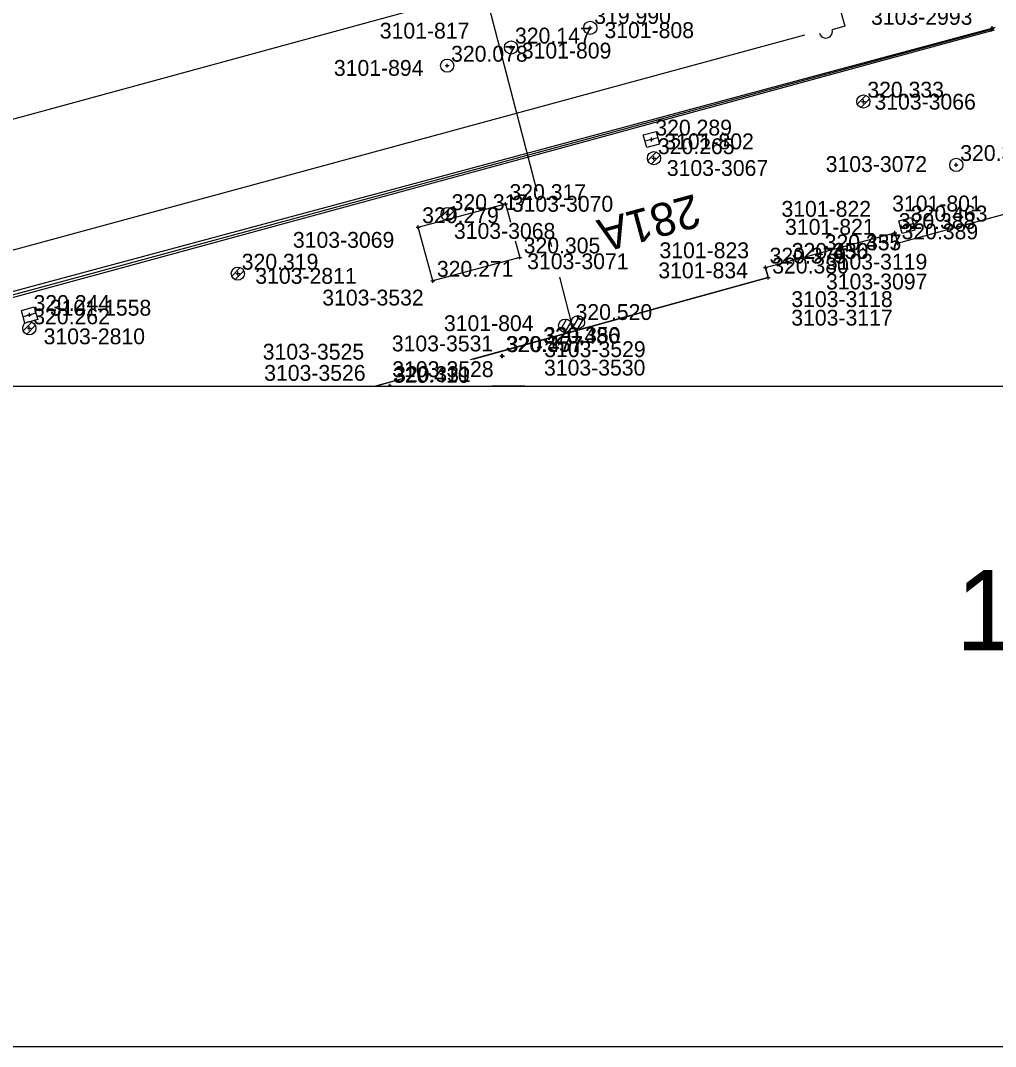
# Model space of a CAD drawing. Extents: x -821875 to -821475, y -1070280 to -1069975.
# Drawn here: x -821717.84 to -821680.94, y -1070275 to -1070236.16 of the extents above; entities that cross this region are included whole.
import ezdxf

# ---------------------------------------------------------------- set-up
doc = ezdxf.new("R2010")
doc.units = 0
for name, color, linetype in [('Vrstva 1', 7, 'Continuous'), ('Vrstva 11', 7, 'Continuous'), ('Vrstva 14', 7, 'Continuous'), ('Vrstva 23', 7, 'Continuous'), ('Vrstva 25', 7, 'Continuous'), ('Vrstva 3', 7, 'Continuous'), ('Vrstva 36', 7, 'Continuous'), ('Vrstva 41', 7, 'Continuous'), ('Vrstva 43', 7, 'Continuous'), ('Vrstva 47', 7, 'Continuous'), ('Vrstva 52', 7, 'Continuous'), ('Vrstva 60', 7, 'Continuous'), ('Vrstva 61', 7, 'Continuous')]:
    doc.layers.add(name, color=color, linetype=linetype)

# ---------------------------------------------------------------- blocks, each defined once
blk = doc.blocks.new('BOD')
at = {"layer": 'Vrstva 3'}
for p, q in [((-0.15, 0), (0.15, 0)), ((0, -0.15), (0, 0.15))]:
    blk.add_line(p, q, dxfattribs=at)

msp = doc.modelspace()

# ---------------------------------------------------------------- linework, layer by layer
at = {"layer": 'Vrstva 1'}
for points in [[(-821475, -1069975), (-821875, -1069975), (-821875, -1070275), (-821475, -1070275)], [(-821500, -1070000), (-821850, -1070000), (-821850, -1070250), (-821500, -1070250)], [(-821500, -1070000), (-821850, -1070000), (-821850, -1070250), (-821500, -1070250)]]:
    msp.add_lwpolyline(points, close=True, dxfattribs=at)
for points in [[(-821667.464, -1070226.079), (-821669.621, -1070226.661), (-821739.032, -1070245.599)], [(-821688.161, -1070236.716), (-821726.868, -1070247.228)], [(-821701.25, -1070250), (-821700, -1070250)], [(-821700, -1070250), (-821698.75, -1070250), (-821700, -1070250)]]:
    msp.add_lwpolyline(points, dxfattribs=at)
msp.add_spline([(-821710.276, -1070200.761), (-821741.264, -1070209.238), (-821760.235, -1070214.402), (-821776.338, -1070219.041), (-821794.464, -1070225.772), (-821811.866, -1070233.595), (-821823.5, -1070239.204)], degree=3, dxfattribs=at)
at = {"layer": 'Vrstva 11'}
for p, q in [((-821703.558, -1070222.406), (-821698.291, -1070242.616)), ((-821697.793, -1070244.529), (-821697.746, -1070244.709)), ((-821697.441, -1070245.88), (-821696.981, -1070247.646)), ((-821697.172, -1070247.468), (-821697.408, -1070247.878)), ((-821697.016, -1070247.572), (-821697.239, -1070247.96)), ((-821696.688, -1070247.338), (-821696.924, -1070247.749)), ((-821696.532, -1070247.443), (-821696.754, -1070247.829))]:
    msp.add_line(p, q, dxfattribs=at)
for centre in [(-821697.222, -1070247.711), (-821697.222, -1070247.711), (-821696.74, -1070247.581), (-821696.74, -1070247.581)]:
    msp.add_circle(centre, 0.25, dxfattribs=at)
at = {"layer": 'Vrstva 14'}
for p, q in [((-821680.981, -1070236.519), (-821730.446, -1070250)), ((-821724.263, -1070248.063), (-821681.061, -1070236.453)), ((-821681.085, -1070236.494), (-821723.536, -1070248.016)), ((-821681.085, -1070236.494), (-821681.047, -1070236.484)), ((-821680.942, -1070236.42), (-821681.061, -1070236.453))]:
    msp.add_line(p, q, dxfattribs=at)
for points in [[(-821702.787, -1070243.981), (-821699.482, -1070243.105), (-821699.299, -1070243.792)], [(-821699.111, -1070244.502), (-821698.945, -1070245.125), (-821702.231, -1070246.01), (-821702.787, -1070243.981)]]:
    msp.add_lwpolyline(points, dxfattribs=at)
at = {"layer": 'Vrstva 23'}
for points in [[(-821684.746, -1070244.201), (-821684.641, -1070244.592), (-821669.935, -1070240.588), (-821668.108, -1070247.182)], [(-821689.637, -1070245.511), (-821684.746, -1070244.201)], [(-821689.637, -1070245.511), (-821689.536, -1070245.887), (-821700.819, -1070249.007)], [(-821703.448, -1070249.734), (-821704.409, -1070250)]]:
    msp.add_lwpolyline(points, dxfattribs=at)
at = {"layer": 'Vrstva 25'}
for p, q in [((-821696.299, -1070236.438), (-821696.249, -1070236.438)), ((-821699.299, -1070237.18), (-821699.249, -1070237.18)), ((-821701.718, -1070237.868), (-821701.668, -1070237.868))]:
    msp.add_line(p, q, dxfattribs=at)
for centre in [(-821696.274, -1070236.438), (-821699.274, -1070237.18), (-821701.693, -1070237.868)]:
    msp.add_circle(centre, 0.25, dxfattribs=at)
at = {"layer": 'Vrstva 36'}
for p, q in [((-821686.168, -1070239.32), (-821685.844, -1070238.997)), ((-821686.038, -1070239.455), (-821685.71, -1070239.128)), ((-821694.094, -1070241.46), (-821693.772, -1070241.137)), ((-821693.964, -1070241.595), (-821693.637, -1070241.268)), ((-821701.904, -1070243.579), (-821701.58, -1070243.256)), ((-821701.774, -1070243.714), (-821701.446, -1070243.386)), ((-821709.848, -1070245.833), (-821709.526, -1070245.51)), ((-821709.718, -1070245.968), (-821709.391, -1070245.64)), ((-821717.738, -1070247.902), (-821717.416, -1070247.579)), ((-821717.608, -1070248.037), (-821717.281, -1070247.71))]:
    msp.add_line(p, q, dxfattribs=at)
for centre in [(-821685.937, -1070239.228), (-821693.864, -1070241.368), (-821701.673, -1070243.487), (-821709.618, -1070245.741), (-821717.508, -1070247.81)]:
    msp.add_circle(centre, 0.25, dxfattribs=at)
at = {"layer": 'Vrstva 41'}
for p, q in [((-821687.295, -1070233.964), (-821686.637, -1070236.376)), ((-821686.637, -1070236.376), (-821687.12, -1070236.507))]:
    msp.add_line(p, q, dxfattribs=at)
msp.add_arc((-821687.359, -1070236.578), 0.25, 194.1154, 16.4069, dxfattribs=at)
at = {"layer": 'Vrstva 43'}
for points in [[(-821693.719, -1070240.599), (-821693.654, -1070240.841), (-821694.138, -1070240.971), (-821694.268, -1070240.487), (-821693.784, -1070240.357), (-821693.719, -1070240.599), (-821694.203, -1070240.729)], [(-821684.048, -1070243.853), (-821683.983, -1070244.094), (-821684.465, -1070244.224), (-821684.595, -1070243.742), (-821684.113, -1070243.612), (-821684.048, -1070243.853), (-821684.53, -1070243.983)], [(-821717.26, -1070247.238), (-821717.192, -1070247.478), (-821717.673, -1070247.613), (-821717.808, -1070247.132), (-821717.327, -1070246.997), (-821717.26, -1070247.238), (-821717.74, -1070247.372)]]:
    msp.add_lwpolyline(points, dxfattribs=at)
at = {"layer": 'Vrstva 47'}
msp.add_circle((-821682.42, -1070241.626), 0.25, dxfattribs=at)
at = {"layer": 'Vrstva 52'}
for points in [[(-821700.708, -1070248.976), (-821689.536, -1070245.887), (-821689.637, -1070245.511), (-821684.746, -1070244.201), (-821684.641, -1070244.592), (-821669.935, -1070240.588), (-821668.108, -1070247.182), (-821671.404, -1070248.095), (-821670.899, -1070250)], [(-821704.409, -1070250), (-821703.336, -1070249.703)]]:
    msp.add_lwpolyline(points, dxfattribs=at)
at = {"layer": 'Vrstva 60'}
for p, q in [((-821703.891, -1070250), (-821703.891, -1070249.949)), ((-821703.85, -1070250), (-821703.85, -1070249.92)), ((-821703.925, -1070249.995), (-821703.775, -1070249.995))]:
    msp.add_line(p, q, dxfattribs=at)

# ---------------------------------------------------------------- block references
at = {"layer": 'Vrstva 60', "xscale": 0.5, "yscale": 0.5}
for p in [(-821696.274, -1070236.438), (-821681.061, -1070236.453), (-821681.085, -1070236.494), (-821699.274, -1070237.18), (-821701.693, -1070237.868), (-821685.937, -1070239.228), (-821693.961, -1070240.664), (-821693.864, -1070241.368), (-821682.42, -1070241.626), (-821699.482, -1070243.105), (-821701.673, -1070243.487), (-821702.787, -1070243.981), (-821684.746, -1070244.201), (-821684.289, -1070243.918), (-821684.641, -1070244.592), (-821698.945, -1070245.125), (-821688.799, -1070245.332), (-821688.796, -1070245.334), (-821687.553, -1070245.01), (-821687.549, -1070245.005), (-821709.618, -1070245.741), (-821689.637, -1070245.511), (-821702.231, -1070246.01), (-821689.536, -1070245.887), (-821717.5, -1070247.305), (-821696.981, -1070247.646), (-821717.508, -1070247.81), (-821699.623, -1070248.856), (-821699.591, -1070248.862), (-821698.207, -1070248.541), (-821698.181, -1070248.516)]:
    msp.add_blockref('BOD', p, dxfattribs=at)

# ---------------------------------------------------------------- texts
at = {"layer": 'Vrstva 1'}
msp.add_text('1 : 500', height=3.04, dxfattribs=at).set_placement((-821682.432, -1070260))
at = {"layer": 'Vrstva 11'}
msp.add_text('281A', height=1.25, rotation=195.1164, dxfattribs=at).set_placement((-821692.324, -1070242.718))
at = {"layer": 'Vrstva 60'}
for s, p in [('3103-2993', (-821685.646, -1070236.322)), ('3101-817', (-821704.241, -1070236.843)), ('3101-808', (-821695.738, -1070236.824)), ('3101-809', (-821698.867, -1070237.598)), ('3101-894', (-821705.979, -1070238.254)), ('3103-3066', (-821685.517, -1070239.533)), ('3101-802', (-821693.473, -1070241.034)), ('3103-3072', (-821687.363, -1070241.894)), ('3103-3067', (-821693.376, -1070242.043)), ('3103-3070', (-821699.243, -1070243.399)), ('3101-822', (-821689.037, -1070243.59)), ('3101-801', (-821684.847, -1070243.388)), ('3101-821', (-821688.9, -1070244.271)), ('3103-3068', (-821701.434, -1070244.425)), ('3103-3069', (-821707.53, -1070244.764)), ('3101-823', (-821693.654, -1070245.158)), ('3103-3071', (-821698.662, -1070245.575)), ('3101-834', (-821693.698, -1070245.919)), ('3103-3119', (-821687.355, -1070245.589)), ('3103-2811', (-821708.953, -1070246.127)), ('3103-3097', (-821687.351, -1070246.34)), ('3103-3532', (-821706.417, -1070246.949)), ('3103-3118', (-821688.663, -1070247.006)), ('3101-1558', (-821716.73, -1070247.333)), ('3103-3117', (-821688.665, -1070247.71)), ('3101-804', (-821701.813, -1070247.918)), ('3103-2810', (-821716.966, -1070248.416)), ('3103-3525', (-821708.672, -1070248.998)), ('3103-3531', (-821703.786, -1070248.685)), ('3103-3529', (-821698.015, -1070248.902)), ('3103-3526', (-821708.617, -1070249.8)), ('3103-3528', (-821703.77, -1070249.659)), ('3103-3530', (-821698.025, -1070249.601))]:
    msp.add_text(s, height=0.6, dxfattribs=at).set_placement(p)
at = {"layer": 'Vrstva 61'}
for s, p in [('319.990', (-821696.124, -1070236.288)), ('320.147', (-821699.124, -1070237.03)), ('320.078', (-821701.543, -1070237.718)), ('320.333', (-821685.787, -1070239.078)), ('320.289', (-821693.811, -1070240.514)), ('320.265', (-821693.714, -1070241.218)), ('320.320', (-821682.27, -1070241.476)), ('320.317', (-821699.332, -1070242.955)), ('320.317', (-821701.523, -1070243.337)), ('320.279', (-821702.637, -1070243.831)), ('320.463', (-821684.139, -1070243.768)), ('320.388', (-821684.596, -1070244.051)), ('320.389', (-821684.491, -1070244.442)), ('320.305', (-821698.795, -1070244.975)), ('320.435', (-821687.403, -1070244.86)), ('320.357', (-821687.399, -1070244.855)), ('320.379', (-821689.487, -1070245.361)), ('320.350', (-821688.649, -1070245.182)), ('320.436', (-821688.646, -1070245.184)), ('320.319', (-821709.468, -1070245.591)), ('320.271', (-821702.081, -1070245.86)), ('320.380', (-821689.386, -1070245.737)), ('320.244', (-821717.35, -1070247.155)), ('320.262', (-821717.358, -1070247.66)), ('320.520', (-821696.831, -1070247.496)), ('320.486', (-821698.057, -1070248.391)), ('320.350', (-821698.031, -1070248.366)), ('320.357', (-821699.473, -1070248.706)), ('320.477', (-821699.441, -1070248.712)), ('320.410', (-821703.741, -1070249.874)), ('320.331', (-821703.7, -1070249.845))]:
    msp.add_text(s, height=0.6, dxfattribs=at).set_placement(p)

doc.saveas('drawing.dxf')
